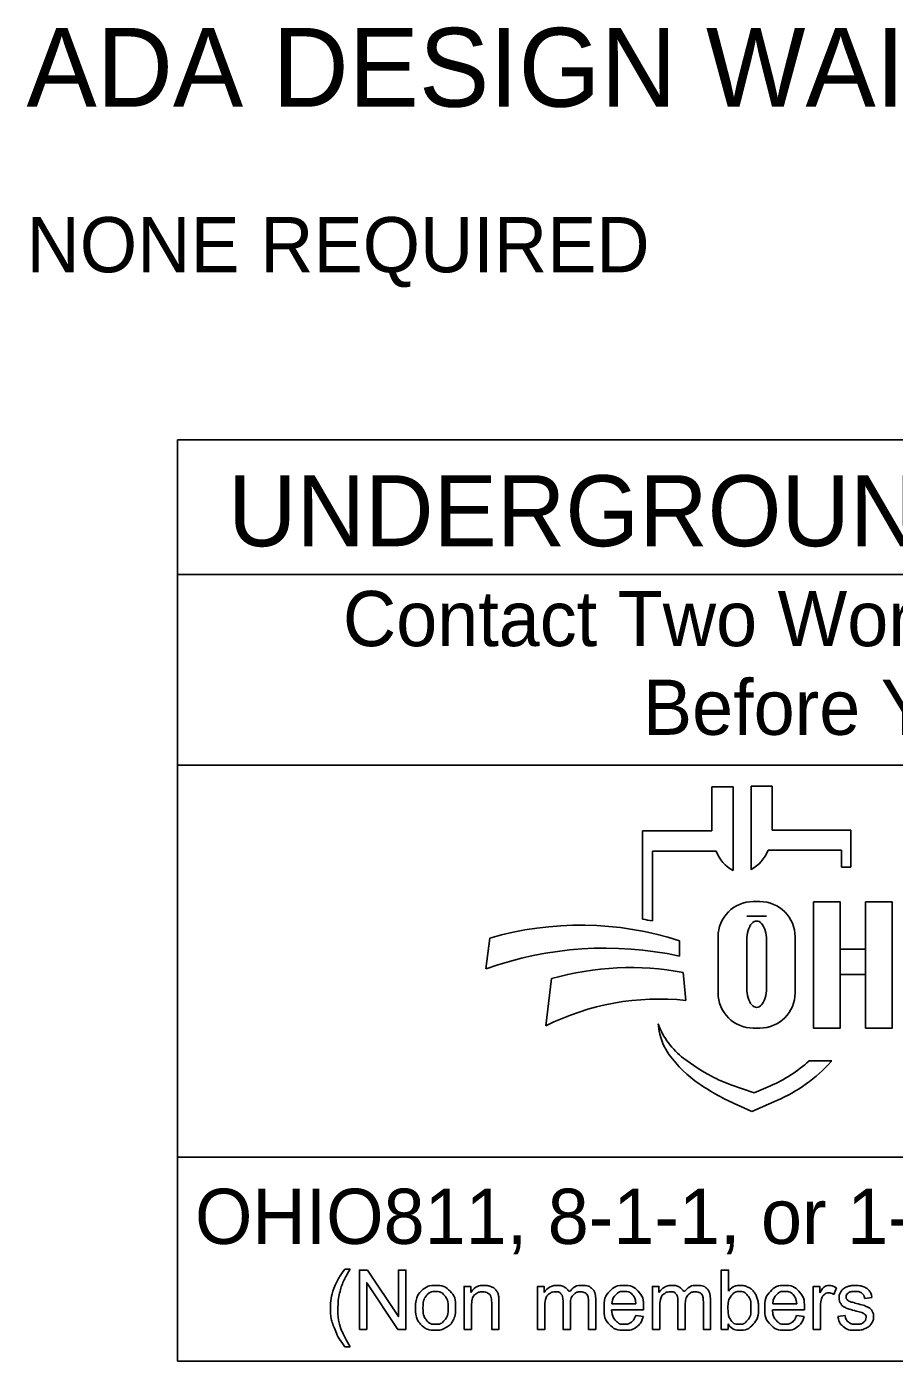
# Model space of a CAD drawing. Extents: x 0 to 39.4, y 0 to 22.
# Drawn here: x 1.995 to 4.196, y 2.143 to 5.529 of the extents above; entities that cross this region are included whole.
import ezdxf

# ---------------------------------------------------------------- set-up
doc = ezdxf.new("R2010")
doc.units = 0
doc.layers.add('SH_Data', color=7, linetype='Continuous')
doc.layers.add('SH_Text', color=7, linetype='Continuous')

msp = doc.modelspace()

# ---------------------------------------------------------------- linework, layer by layer
at = {"layer": 'SH_Data'}
for p, q in [((2.3775, 2.1428), (2.3775, 4.4803)), ((6.6275, 4.4803), (2.3775, 4.4803)), ((2.3775, 4.1387), (6.6275, 4.1387)), ((2.3775, 3.6553), (6.6275, 3.6553)), ((6.6275, 2.6607), (2.3775, 2.6607)), ((6.6275, 2.1428), (2.3775, 2.1428))]:
    msp.add_line(p, q, dxfattribs=at)
at = {"layer": 'SH_Text'}
for p, q in [((3.7335, 3.4883), (3.7335, 3.5998)), ((3.7335, 3.5998), (3.7872, 3.5998)), ((3.7872, 3.5998), (3.7872, 3.3877)), ((3.8329, 3.39), (3.8329, 3.6021)), ((3.8329, 3.6021), (3.8865, 3.6021)), ((3.8865, 3.6021), (3.8865, 3.4906)), ((3.5576, 3.2644), (3.5576, 3.4883)), ((3.5576, 3.4883), (3.7335, 3.4883)), ((3.8865, 3.4906), (4.0857, 3.4906)), ((4.0857, 3.4906), (4.0857, 3.3968)), ((3.5828, 3.4369), (3.5828, 3.26)), ((3.7439, 3.4369), (3.5828, 3.4369)), ((4.0625, 3.4392), (3.8761, 3.4392)), ((4.0625, 3.3968), (4.0625, 3.4392)), ((4.0857, 3.3968), (4.0625, 3.3968)), ((3.8385, 3.3091), (3.8551, 3.3091)), ((3.8718, 3.2721), (3.822, 3.2721)), ((3.7491, 3.0776), (3.7491, 3.2196)), ((3.9445, 3.2196), (3.9445, 3.0776)), ((3.1602, 3.1381), (3.1696, 3.2162)), ((3.6509, 3.2097), (3.6509, 3.1709)), ((3.822, 3.089), (3.822, 3.2114)), ((3.8718, 3.2114), (3.8718, 3.089)), ((3.6608, 3.1291), (3.6671, 3.0582)), ((3.312, 2.9936), (3.3267, 3.1137)), ((3.5997, 2.9807), (3.5967, 2.9986)), ((3.8551, 2.9882), (3.8385, 2.9882)), ((3.98, 2.9048), (4.0375, 2.9048)), ((3.7816, 2.8444), (3.841, 2.8239)), ((3.841, 2.8239), (3.8821, 2.8417)), ((3.835, 2.7769), (3.7976, 2.7934)), ((3.8983, 2.8044), (3.835, 2.7769))]:
    msp.add_line(p, q, dxfattribs=at)
for points in [[(3.991, 3.3081), (4.0589, 3.3081), (4.0589, 2.9881), (3.991, 2.9881)], [(4.1231, 3.3081), (4.1911, 3.3081), (4.1911, 2.9881), (4.1231, 2.9881)], [(4.0589, 3.1882), (4.1231, 3.1882), (4.1231, 3.1242), (4.0589, 3.1242)]]:
    msp.add_lwpolyline(points, close=True, dxfattribs=at)
for points in [[(2.8021, 2.3766), (2.8153, 2.3766)], [(2.8389, 2.2239), (2.8389, 2.3741), (2.8592, 2.3741), (2.9382, 2.2561), (2.9382, 2.3741), (2.9572, 2.3741), (2.9572, 2.2239), (2.9369, 2.2239), (2.8579, 2.3419), (2.8579, 2.2239), (2.8389, 2.2239)], [(3.7743, 2.2239), (3.7573, 2.2239), (3.7573, 2.3741), (3.7757, 2.3741), (3.7757, 2.3206)], [(3.1048, 2.2239), (3.1048, 2.3328), (3.1214, 2.3328), (3.1214, 2.3173)], [(3.2912, 2.2239), (3.2912, 2.3328), (3.3077, 2.3328), (3.3077, 2.3174)], [(3.5826, 2.2239), (3.5826, 2.3328), (3.5991, 2.3328), (3.5991, 2.3174)], [(3.9904, 2.2239), (3.9904, 2.3328), (4.007, 2.3328), (4.007, 2.3163)], [(4.0495, 2.3293), (4.043, 2.3122)], [(4.1394, 2.3046), (4.1213, 2.3022)], [(3.1233, 2.2833), (3.1233, 2.2239), (3.1048, 2.2239)], [(3.1932, 2.2908), (3.1932, 2.2239), (3.1748, 2.2239), (3.1748, 2.2901)], [(3.3097, 2.2803), (3.3097, 2.2239), (3.2912, 2.2239)], [(3.3743, 2.2871), (3.3743, 2.2239), (3.3559, 2.2239), (3.3559, 2.2946)], [(3.4388, 2.2986), (3.4388, 2.2239), (3.4203, 2.2239), (3.4203, 2.2924)], [(3.56, 2.2736), (3.4788, 2.2736)], [(3.4799, 2.2887), (3.5406, 2.2887)], [(3.601, 2.2803), (3.601, 2.2239), (3.5826, 2.2239)], [(3.6657, 2.2871), (3.6657, 2.2239), (3.6473, 2.2239), (3.6473, 2.2946)], [(3.7301, 2.2986), (3.7301, 2.2239), (3.7117, 2.2239), (3.7117, 2.2924)], [(3.968, 2.2736), (3.8868, 2.2736)], [(3.8879, 2.2887), (3.9486, 2.2887)], [(4.0088, 2.2809), (4.0088, 2.2239), (3.9904, 2.2239)], [(3.5404, 2.2591), (3.5595, 2.2567)], [(3.7743, 2.2375), (3.7743, 2.2239)], [(3.9484, 2.2591), (3.9675, 2.2567)], [(4.053, 2.2564), (4.0712, 2.2593)], [(2.8153, 2.1798), (2.8021, 2.1798)]]:
    msp.add_lwpolyline(points, dxfattribs=at)
for centre, radius, start, end in [((3.8353, 3.4736), 0.0985, 201.9296, 240.7469), ((3.7847, 3.476), 0.0985, 299.2531, 338.0704), ((3.8385, 3.2196), 0.0895, 90, 180), ((3.8551, 3.2196), 0.0895, 0, 90), ((3.4295, 2.4554), 0.8191, 79.2074, 81.0007), ((3.3997, 2.4302), 0.8191, 72.1402, 106.3144), ((3.4628, 2.2991), 0.8919, 77.8238, 109.8274), ((3.5267, 2.4094), 0.7322, 79.44, 105.8467), ((3.5987, 2.4262), 0.6357, 83.8248, 116.8021), ((3.8385, 3.0776), 0.0895, 180, 270), ((3.8551, 3.0776), 0.0895, 270, 0), ((3.7841, 3.0707), 0.2008, 201.0457, 232.5314), ((3.741, 3.0048), 0.1433, 189.6817, 216.0884), ((3.8747, 3.1022), 0.3088, 216.0884, 235.7167), ((3.9766, 3.3219), 0.5173, 232.5314, 241.794), ((3.7387, 3.1722), 0.3602, 293.4582, 312.0712), ((3.7387, 3.1722), 0.401, 293.4582, 317.8286), ((4.0412, 3.3465), 0.6044, 235.7167, 246.2325), ((3.8914, 3.1631), 0.3371, 241.794, 250.9821)]:
    msp.add_arc(centre, radius, start, end, dxfattribs=at)
for centre, start_param, end_param in [((3.8469, 3.2114), 4.712389, 7.853982), ((3.8469, 3.089), 1.570796, 4.712389)]:
    msp.add_ellipse(centre, major_axis=(0, 0.0484), ratio=0.514403, start_param=start_param, end_param=end_param, dxfattribs=at)
for points in [[(2.8021, 2.1798), (2.7869, 2.199), (2.7763, 2.2248), (2.7657, 2.2506), (2.7657, 2.2783), (2.7657, 2.3026), (2.7736, 2.325), (2.7829, 2.3509), (2.8021, 2.3766)], [(2.8153, 2.3766), (2.8029, 2.3553), (2.7989, 2.3462), (2.7927, 2.332), (2.7891, 2.3167), (2.7847, 2.2975), (2.7847, 2.2782), (2.7847, 2.2289), (2.8153, 2.1798)], [(2.9814, 2.2783), (2.9814, 2.3085), (2.9981, 2.3231), (3.0122, 2.3352), (3.0323, 2.3352), (3.0547, 2.3352), (3.069, 2.3205), (3.0832, 2.3058), (3.0832, 2.2799), (3.0832, 2.2589), (3.0769, 2.2469), (3.0706, 2.2348), (3.0586, 2.2282), (3.0466, 2.2215), (3.0323, 2.2215), (3.0095, 2.2215), (2.9954, 2.2362), (2.9814, 2.2508), (2.9814, 2.2783)], [(3.0003, 2.2783), (3.0003, 2.2574), (3.0094, 2.247), (3.0185, 2.2366), (3.0323, 2.2366), (3.046, 2.2366), (3.0551, 2.2471), (3.0642, 2.2575), (3.0642, 2.279), (3.0642, 2.2991), (3.0551, 2.3095), (3.0459, 2.3199), (3.0323, 2.3199), (3.0185, 2.3199), (3.0094, 2.3096), (3.0003, 2.2992), (3.0003, 2.2783)], [(3.1214, 2.3173), (3.1334, 2.3352), (3.156, 2.3352), (3.1659, 2.3352), (3.1741, 2.3316), (3.1823, 2.3281), (3.1864, 2.3224), (3.1905, 2.3166), (3.1922, 2.3087), (3.1932, 2.3036), (3.1932, 2.2908)], [(3.1748, 2.2901), (3.1748, 2.3013), (3.1726, 2.3069), (3.1705, 2.3125), (3.165, 2.3158), (3.1595, 2.3191), (3.1521, 2.3191), (3.1404, 2.3191), (3.1318, 2.3117), (3.1233, 2.3042), (3.1233, 2.2833)], [(3.3077, 2.3174), (3.3128, 2.3254), (3.3214, 2.3303), (3.3299, 2.3352), (3.3407, 2.3352), (3.3528, 2.3352), (3.3606, 2.3301), (3.3683, 2.3251), (3.3715, 2.3161), (3.3844, 2.3352), (3.4051, 2.3352), (3.4213, 2.3352), (3.43, 2.3262), (3.4388, 2.3172), (3.4388, 2.2986)], [(3.3559, 2.2946), (3.3559, 2.3069), (3.3514, 2.313), (3.3469, 2.3191), (3.3366, 2.3191), (3.3288, 2.3191), (3.3222, 2.315), (3.3156, 2.311), (3.3126, 2.3031), (3.3097, 2.2952), (3.3097, 2.2803)], [(3.4203, 2.2924), (3.4203, 2.3035), (3.4185, 2.3083), (3.4168, 2.3132), (3.412, 2.3162), (3.4073, 2.3191), (3.401, 2.3191), (3.3895, 2.3191), (3.3819, 2.3115), (3.3743, 2.3039), (3.3743, 2.2871)], [(3.5595, 2.2567), (3.555, 2.24), (3.5428, 2.2307), (3.5306, 2.2215), (3.5117, 2.2215), (3.4878, 2.2215), (3.4738, 2.2362), (3.4598, 2.2509), (3.4598, 2.2774), (3.4598, 2.3049), (3.474, 2.32), (3.4881, 2.3352), (3.5106, 2.3352), (3.5324, 2.3352), (3.5463, 2.3203), (3.5601, 2.3055), (3.5601, 2.2785), (3.5601, 2.2769), (3.56, 2.2736)], [(3.5406, 2.2887), (3.5394, 2.3025), (3.5337, 2.3094), (3.5249, 2.3201), (3.5108, 2.3201), (3.4981, 2.3201), (3.4894, 2.3115), (3.4808, 2.303), (3.4799, 2.2887)], [(3.5991, 2.3174), (3.6042, 2.3254), (3.6127, 2.3303), (3.6212, 2.3352), (3.6321, 2.3352), (3.6442, 2.3352), (3.6519, 2.3301), (3.6597, 2.3251), (3.6628, 2.3161), (3.6758, 2.3352), (3.6965, 2.3352), (3.7127, 2.3352), (3.7214, 2.3262), (3.7301, 2.3172), (3.7301, 2.2986)], [(3.6473, 2.2946), (3.6473, 2.3069), (3.6428, 2.313), (3.6383, 2.3191), (3.628, 2.3191), (3.6202, 2.3191), (3.6136, 2.315), (3.607, 2.311), (3.604, 2.3031), (3.601, 2.2952), (3.601, 2.2803)], [(3.7117, 2.2924), (3.7117, 2.3035), (3.7099, 2.3083), (3.7081, 2.3132), (3.7034, 2.3162), (3.6987, 2.3191), (3.6923, 2.3191), (3.6809, 2.3191), (3.6733, 2.3115), (3.6657, 2.3039), (3.6657, 2.2871)], [(3.7741, 2.2792), (3.7741, 2.2596), (3.7794, 2.2509), (3.7881, 2.2366), (3.8029, 2.2366), (3.815, 2.2366), (3.8238, 2.2471), (3.8326, 2.2576), (3.8326, 2.2784), (3.8326, 2.2998), (3.8241, 2.3099), (3.8157, 2.3201), (3.8038, 2.3201), (3.7917, 2.3201), (3.7829, 2.3096), (3.7741, 2.299), (3.7741, 2.2792)], [(3.7757, 2.3206), (3.7874, 2.3352), (3.8055, 2.3352), (3.8155, 2.3352), (3.8245, 2.3311), (3.8335, 2.3271), (3.8392, 2.3198), (3.845, 2.3124), (3.8483, 2.3021), (3.8516, 2.2918), (3.8516, 2.28), (3.8516, 2.252), (3.8378, 2.2368), (3.8239, 2.2215), (3.8046, 2.2215), (3.7853, 2.2215), (3.7743, 2.2375)], [(3.9675, 2.2567), (3.963, 2.24), (3.9508, 2.2307), (3.9386, 2.2215), (3.9196, 2.2215), (3.8958, 2.2215), (3.8818, 2.2362), (3.8678, 2.2509), (3.8678, 2.2774), (3.8678, 2.3049), (3.882, 2.32), (3.8961, 2.3352), (3.9186, 2.3352), (3.9404, 2.3352), (3.9543, 2.3203), (3.9681, 2.3055), (3.9681, 2.2785), (3.9681, 2.2769), (3.968, 2.2736)], [(3.9486, 2.2887), (3.9474, 2.3025), (3.9417, 2.3094), (3.9328, 2.3201), (3.9188, 2.3201), (3.9061, 2.3201), (3.8974, 2.3115), (3.8888, 2.303), (3.8879, 2.2887)], [(4.007, 2.3163), (4.0133, 2.3278), (4.0187, 2.3315), (4.0241, 2.3352), (4.0305, 2.3352), (4.0398, 2.3352), (4.0495, 2.3293)], [(4.043, 2.3122), (4.0363, 2.3162), (4.0295, 2.3162), (4.0235, 2.3162), (4.0187, 2.3125), (4.0139, 2.3089), (4.0119, 2.3024), (4.0088, 2.2926), (4.0088, 2.2809)], [(4.1213, 2.3022), (4.1201, 2.3106), (4.1142, 2.3153), (4.1083, 2.3201), (4.0975, 2.3201), (4.0848, 2.3201), (4.0794, 2.3159), (4.0739, 2.3116), (4.0739, 2.306), (4.0739, 2.3024), (4.0762, 2.2995), (4.0785, 2.2966), (4.0833, 2.2946), (4.086, 2.2936), (4.0996, 2.2899), (4.1192, 2.2847), (4.1269, 2.2813), (4.1347, 2.278), (4.1391, 2.2717), (4.1435, 2.2653), (4.1435, 2.2559), (4.1435, 2.2467), (4.1381, 2.2386), (4.1327, 2.2304), (4.1226, 2.226), (4.1124, 2.2215), (4.0996, 2.2215), (4.0784, 2.2215), (4.0672, 2.2303), (4.0561, 2.2391), (4.053, 2.2564)], [(4.0712, 2.2593), (4.0727, 2.2483), (4.0798, 2.2425), (4.0868, 2.2366), (4.0995, 2.2366), (4.1122, 2.2366), (4.1184, 2.2418), (4.1245, 2.247), (4.1245, 2.254), (4.1245, 2.2602), (4.1191, 2.2638), (4.1153, 2.2663), (4.1002, 2.2701), (4.0799, 2.2752), (4.072, 2.2789), (4.0642, 2.2827), (4.0601, 2.2893), (4.0561, 2.2959), (4.0561, 2.3038), (4.0561, 2.3111), (4.0594, 2.3173), (4.0628, 2.3235), (4.0685, 2.3276), (4.0728, 2.3308), (4.0803, 2.333), (4.0877, 2.3352), (4.0962, 2.3352), (4.109, 2.3352), (4.1187, 2.3315), (4.1284, 2.3278), (4.133, 2.3215), (4.1377, 2.3152), (4.1394, 2.3046)], [(3.4788, 2.2736), (3.4799, 2.2557), (3.489, 2.2462), (3.4981, 2.2366), (3.5117, 2.2366), (3.5219, 2.2366), (3.5291, 2.242), (3.5362, 2.2473), (3.5404, 2.2591)], [(3.8868, 2.2736), (3.8879, 2.2557), (3.897, 2.2462), (3.9061, 2.2366), (3.9197, 2.2366), (3.9299, 2.2366), (3.937, 2.242), (3.9442, 2.2473), (3.9484, 2.2591)]]:
    msp.add_open_spline(points, degree=3, dxfattribs=at)

# ---------------------------------------------------------------- texts
for s, height, p in [('ADA DESIGN WAIVERS', 0.2, (1.9944, 5.3256)), ('NONE REQUIRED', 0.14, (1.9944, 4.9056)), ('UNDERGROUND UTILITIES', 0.18, (2.5057, 4.2106)), ('Contact Two Working Days', 0.14, (2.7972, 3.9571)), ('Before You Dig', 0.14, (3.5583, 3.7321)), ('OHIO811, 8-1-1, or 1-800-362-2764', 0.14, (2.422, 2.4406))]:
    msp.add_text(s, height=height, dxfattribs=at).set_placement(p)

doc.saveas('drawing.dxf')
